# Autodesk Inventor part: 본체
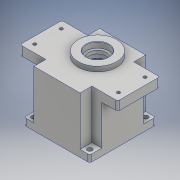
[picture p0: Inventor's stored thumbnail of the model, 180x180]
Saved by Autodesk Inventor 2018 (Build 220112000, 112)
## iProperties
Created: 2020-07
Part Number: 본체
Material: 알루미늄 6061
Document SubType Name: Modeling
Designer: admin
Density: 2.7 g/cm^3
Appearance: 알루미늄 - 평지
Mass: 876.469 g
Surface Area: 793.591 cm^2
Volume: 324.618 cm^3
Author: admin
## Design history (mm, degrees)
sketch "스케치2"
  geometry: L1 (-47, -47)-(47, -47); L2 (47, -47)-(47, 47); L3 (47, 47)-(-47, 47); L4 (-47, 47)-(-47, -47); L5 (-47, -47)-(47, 47); L6 (47, -47)-(-47, 47); 1 further point
  constraints: 12 end point, 2 midpoint, 2 parallel, 1 horizontal, 1 perpendicular
  dimensions: "d0" = 94 distance of L2.end L3.end; "d1" = 94 distance of L1.end L2.end
extrude "돌출1" new body sketch "스케치2" stored distance "d2" = 67; taper "d3" = 0 deg
sketch "스케치3"
  geometry: L1 (-70, -47)-(70, -47); L2 (70, -47)-(70, 47); L3 (70, 47)-(-70, 47); L4 (-70, 47)-(-70, -47); L5 (-70, -47)-(70, 47); L6 (70, -47)-(-70, 47); 1 further point
  constraints: 12 end point, 2 midpoint, 2 parallel, 1 horizontal, 1 perpendicular
  dimensions: "d4" = 140 distance of L2.end L3.end; "d5" = 94 distance of L1.end L2.end
extrude "돌출2" join sketch "스케치3" distance "d6" = 13; taper "d7" = 0 deg
sketch "스케치4"
  geometry: L1 (-70, -47)-(70, -47) reference; L2 (70, -47)-(70, 47) reference; L3 (70, 47)-(-70, 47) reference; L4 (-70, 47)-(-70, -47) reference; L5 (-98, 0)-(98, 0) reference; L6 (0, -65.8)-(0, 65.8) reference; L7 (-70, 47)-(-33, 47); L8 (-33, 47)-(-33, 30); L9 (-33, 30)-(-70, 30); L10 (-70, 30)-(-70, 47); L11 (70, 47)-(33, 47); L12 (70, 30)-(70, 47); L13 (33, 30)-(70, 30); L14 (33, 47)-(33, 30); L15 (-70, -47)-(-33, -47); L16 (-70, -30)-(-70, -47); L17 (-33, -30)-(-70, -30); L18 (-33, -47)-(-33, -30); L19 (33, -47)-(33, -30); L20 (33, -30)-(70, -30); L21 (70, -47)-(33, -47); L22 (70, -30)-(70, -47); 1 further point
  constraints: 32 end point, 9 symmetric about line, 2 parallel, 1 horizontal, 1 perpendicular
  dimensions: "d8" = 17 distance between parallel lines of L3 L9; "d9" = 37 distance between parallel lines of L8 L4
extrude "돌출3" cut sketch "스케치4" distance "d10" = 70; taper "d11" = 0 deg
sketch "스케치5"
  geometry: L1 (0, -65.8)-(0, 65.8) reference; L2 (-98, 0)-(98, 0) reference; C1 r 27.5 at (0, 11); 1 further point
  constraints: 1 centre point, 1 point on line
  dimensions: "d12" = 55 diameter of C1; "d13" = 11 distance from line of C1.centre L2
extrude "돌출4" join sketch "스케치5" distance "d14" = 7; taper "d15" = 0 deg
sketch "스케치6"
  geometry: L1 (0, -76.8)-(0, 54.8) reference; L2 (-98, -11)-(98, -11) reference; C1 r 16 at (0, 0); 1 further point
  constraints: 1 centre point, 1 point on line
  dimensions: "d16" = 32 diameter of C1; "d17" = 11 distance from line of C1.centre L2
extrude "돌출5" cut sketch "스케치6" distance "d18" = 8.3; taper "d19" = 0 deg
sketch "스케치7"
  geometry: L1 (-98, -11)-(98, -11) reference; L2 (0, -76.8)-(0, 54.8) reference; C1 r 12.5 at (0, 0); 1 further point
  constraints: 1 centre point, 1 point on line
  dimensions: "d20" = 25 diameter of C1; "d21" = 11 distance from line of C1.centre L1
extrude "돌출6" cut sketch "스케치7" distance "d22" = 4.7; taper "d23" = 0 deg
sketch "스케치8"
  geometry: C1 r 43 at (0, 0); 1 further point
  constraints: 1 centre point, 1 coincident
  dimensions: "d24" = 86 diameter of C1
extrude "돌출7" cut sketch "스케치8" distance "d25" = 9; taper "d26" = 0 deg
sketch "스케치9"
  geometry: C1 r 40 at (0, 0); 1 further point
  constraints: 1 centre point, 1 coincident
  dimensions: "d27" = 80 diameter of C1
extrude "돌출8" cut sketch "스케치9" distance "d28" = 62; taper "d29" = 0 deg
sketch "스케치10"
  geometry: L1 (98, 0)-(-98, 0) reference; L2 (0, -65.8)-(0, 65.8) reference; C1 r 21 at (0, 11); C2 r 15 at (0, -20); 1 further point
  constraints: 2 centre point, 2 point on line
  dimensions: "d30" = 42 diameter of C1; "d31" = 30 diameter of C2; "d32" = 11 distance from line of C1.centre L1; "d33" = 20 distance from line of C2.centre L1
extrude "돌출9" join sketch "스케치10" distance "d34" = 7; taper "d35" = 0 deg
sketch "스케치11"
  geometry: L1 (98, 0)-(-98, 0) reference; L2 (0, -65.8)-(0, 65.8) reference; C1 r 17.5 at (0, 11); 1 further point
  constraints: 1 centre point, 1 point on line
  dimensions: "d36" = 35 diameter of C1; "d37" = 11 distance from line of C1.centre L1
extrude "돌출10" cut sketch "스케치11" distance "d38" = 10; taper "d39" = 0 deg
sketch "스케치12"
  geometry: L1 (98, 0)-(-98, 0) reference; L2 (0, -65.8)-(0, 65.8) reference; C1 r 11 at (0, -20); 1 further point
  constraints: 1 centre point, 1 point on line
  dimensions: "d40" = 22 diameter of C1; "d41" = 20 distance from line of C1.centre L1
extrude "돌출11" cut sketch "스케치12" distance "d42" = 7; taper "d43" = 0 deg
sketch "스케치13"
  geometry: L1 (98, 20)-(-98, 20) reference; L2 (0, -45.8)-(0, 85.8) reference; C1 r 9.5 at (0, 0); 1 further point
  constraints: 1 centre point, 1 point on line
  dimensions: "d44" = 19 diameter of C1; "d45" = 20 distance from line of C1.centre L1
extrude "돌출12" cut sketch "스케치13" distance "d46" = 3; taper "d47" = 0 deg
sketch "스케치15"
  geometry: L1 (98, 0)-(-98, 0) reference; L2 (0, -65.8)-(0, 65.8) reference; L3 (-35.778, 3.994)-(-39.8, 3.994); L4 (-35.778, -3.994)-(-39.8, -3.994); L5 (35.778, 3.994)-(39.8, 3.994); L6 (35.778, -3.994)-(39.8, -3.994); A1 r 4 centre (-36, 0) between (-36.222, -3.994) and (-36.222, 3.994); A2 r 4 centre (36, 0) between (36.222, 3.994) and (36.222, -3.994); A3 r 40 centre (0, 0) between (-39.8, 3.994) and (-39.8, -3.994) reference; A4 r 40 centre (0, 0) between (-39.8, 3.994) and (-39.8, -3.994); A5 r 40 centre (0, 0) between (39.8, -3.994) and (39.8, 3.994); 1 further point
  constraints: 16 point on circle, 8 end point, 8 point on line, 4 centre point, 1 coincident, 1 horizontal, 1 parallel, 1 symmetric about line, 1 other
  dimensions: "d50" = 8 diameter of A1; "d51" = 8 diameter of A2; "d52" = 72 distance of A2.centre A1.centre; "d53" = 7.98764 distance between parallel lines of L6 L5; "d54" = 7.98764 distance between parallel lines of L4 L3
extrude "돌출13" join sketch "스케치15" distance "d55" = 62; taper "d56" = 0 deg
sketch "스케치17"
  geometry: L1 (98, 0)-(-98, 0) reference; L2 (0, -65.8)-(0, 65.8) reference; L3 (-60, 19)-(60, 19); L4 (60, 19)-(60, -19); L5 (60, -19)-(-60, -19); L6 (-60, -19)-(-60, 19); 5 further points
  constraints: 8 end point, 4 coincident, 2 parallel, 2 symmetric about line, 1 horizontal, 1 perpendicular
  dimensions: "d59" = 120 distance of L3.start L3.end; "d60" = 38 distance of L3.end L4.end
hole "구멍1" sketch "스케치17" at (-60, 19), (-60, -19), (60, -19), (60, 19) diameter "d61" = 4.5; stored, may be unused: countersink angle "d65" = 90 deg, drill point angle "d67" = 0 deg; dims "d62" = 6, "d63" = 10, "d64" = 5, "d66" = 13
sketch "스케치18"
  geometry: L1 (-98, 0)-(98, 0) reference; L2 (0, -65.8)-(0, 65.8) reference; L3 (40, 40)-(-40, 40); L4 (-40, 40)-(-40, -40); L5 (-40, -40)-(40, -40); L6 (40, -40)-(40, 40); 5 further points
  constraints: 8 end point, 4 coincident, 2 parallel, 2 symmetric about line, 1 horizontal, 1 perpendicular
  dimensions: "d68" = 80 distance of L3.start L3.end; "d69" = 80 distance of L5.end L3.start
hole "구멍2" sketch "스케치18" at (-40, 40), (40, 40), (-40, -40), (40, -40) diameter "d70" = 7; stored, may be unused: countersink angle "d74" = 90 deg, drill point angle "d76" = 0 deg; dims "d71" = 6, "d72" = 10, "d73" = 5, "d75" = 10
sketch "스케치19"
  geometry: L1 (98, 0)-(-98, 0) reference; L2 (0, -65.8)-(0, 65.8) reference; 5 further points
  constraints: 2 coincident
hole "구멍3" sketch "스케치19" at (-36, 0), (36, 0) diameter "d77" = 3.242; stored, may be unused: countersink angle "d81" = 90 deg, drill point angle "d83" = 118 deg; dims "d78" = 7, "d79" = 10, "d80" = 5, "d82" = 9
sketch "스케치20"
  geometry: L1 (-51, -33.5)-(145, -33.5) reference; L2 (47, 17.4)-(47, -104.4) reference; L3 (0, 0)-(94, 0) reference; 2 further points
  constraints: 1 other
  dimensions: "d84" = 0 distance from line of point (47, -40) L2; "d85" = 40 distance from line of L3 point (47, -40)
feature "엠보싱1" sketch "스케치20" dims "d0" = 94, "d1" = 94, "d86" = 0.5, "d87" = 0
fillet "모깎기1" dims "d88" = 3
fillet "모깎기2" dims "d89" = 3
fillet "모깎기3" dims "d90" = 3
fillet "모깎기4" dims "d91" = 3
chamfer "모따기1" distance "d92" = 1; stored, may be unused: second distance "d93" = 2, angle "d94" = 45 deg
fillet "모깎기5" dims "d95" = 3
chamfer "모따기2" distance "d96" = 1; stored, may be unused: second distance "d97" = 2, angle "d98" = 45 deg
chamfer "모따기3" distance "d99" = 0.8; stored, may be unused: second distance "d100" = 2, angle "d101" = 30 deg
node "솔리드1"
node "투영된 루프1"
